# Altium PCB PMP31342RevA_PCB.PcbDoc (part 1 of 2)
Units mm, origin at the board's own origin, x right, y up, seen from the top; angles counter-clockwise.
Board outline 170.18 x 93.98 mm, 4 copper layers (Top Layer, Layer 1, Layer 2, Bottom Layer), stack 1.787 mm thick; 134 components, 50 nets, 251 pads, 234 vias.
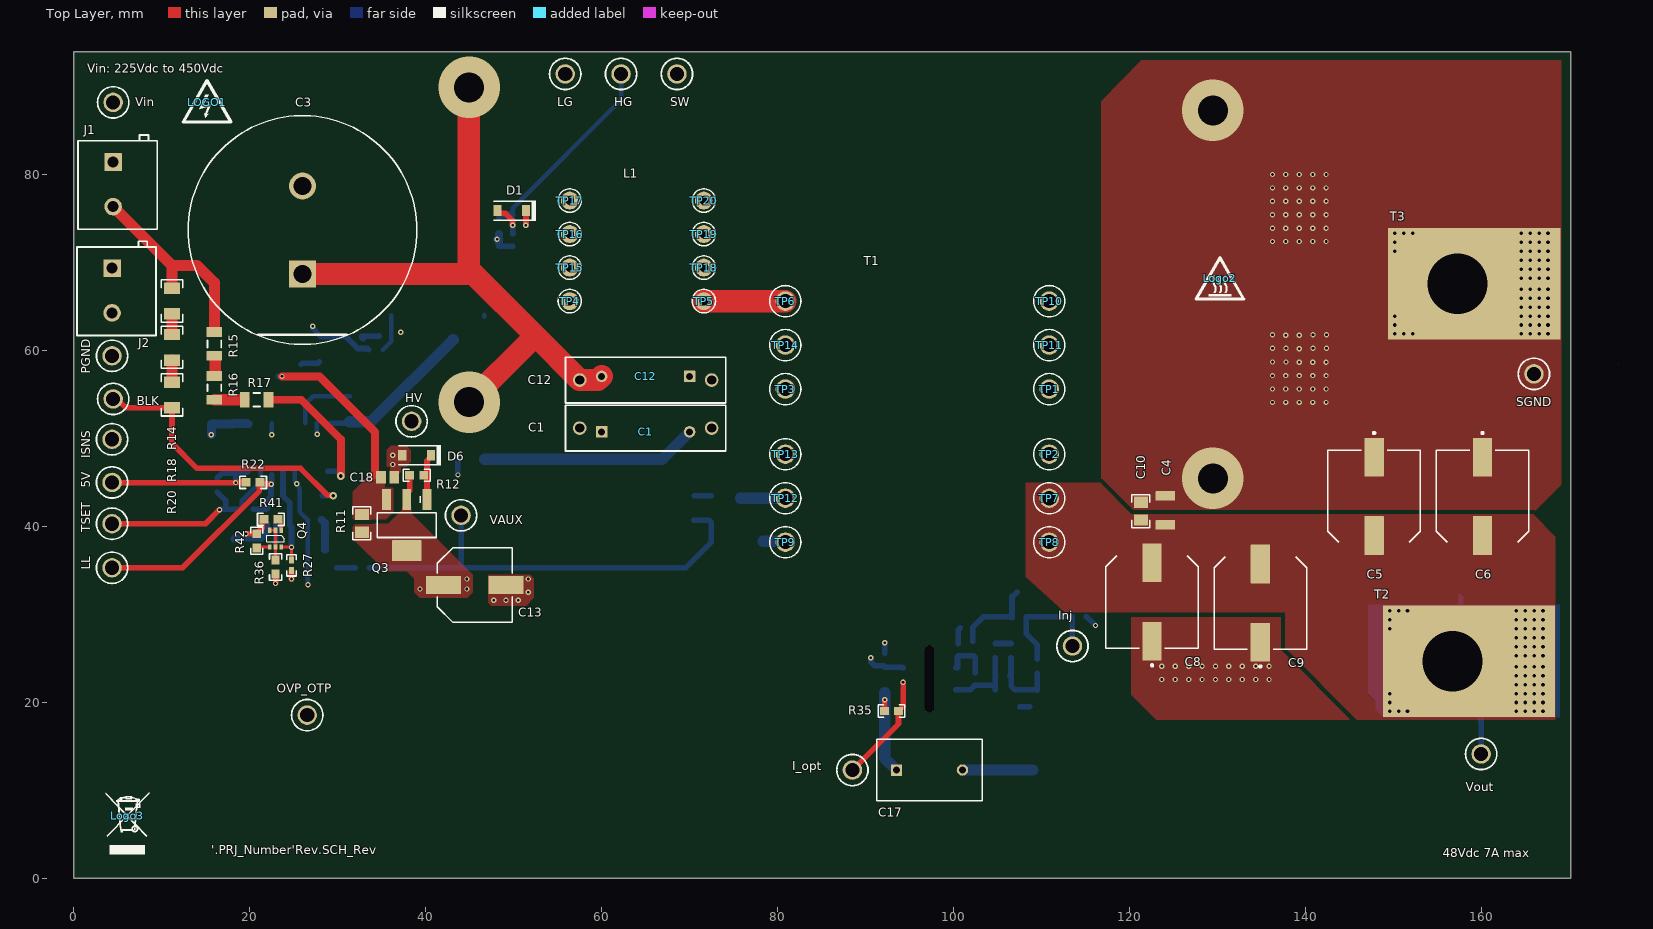
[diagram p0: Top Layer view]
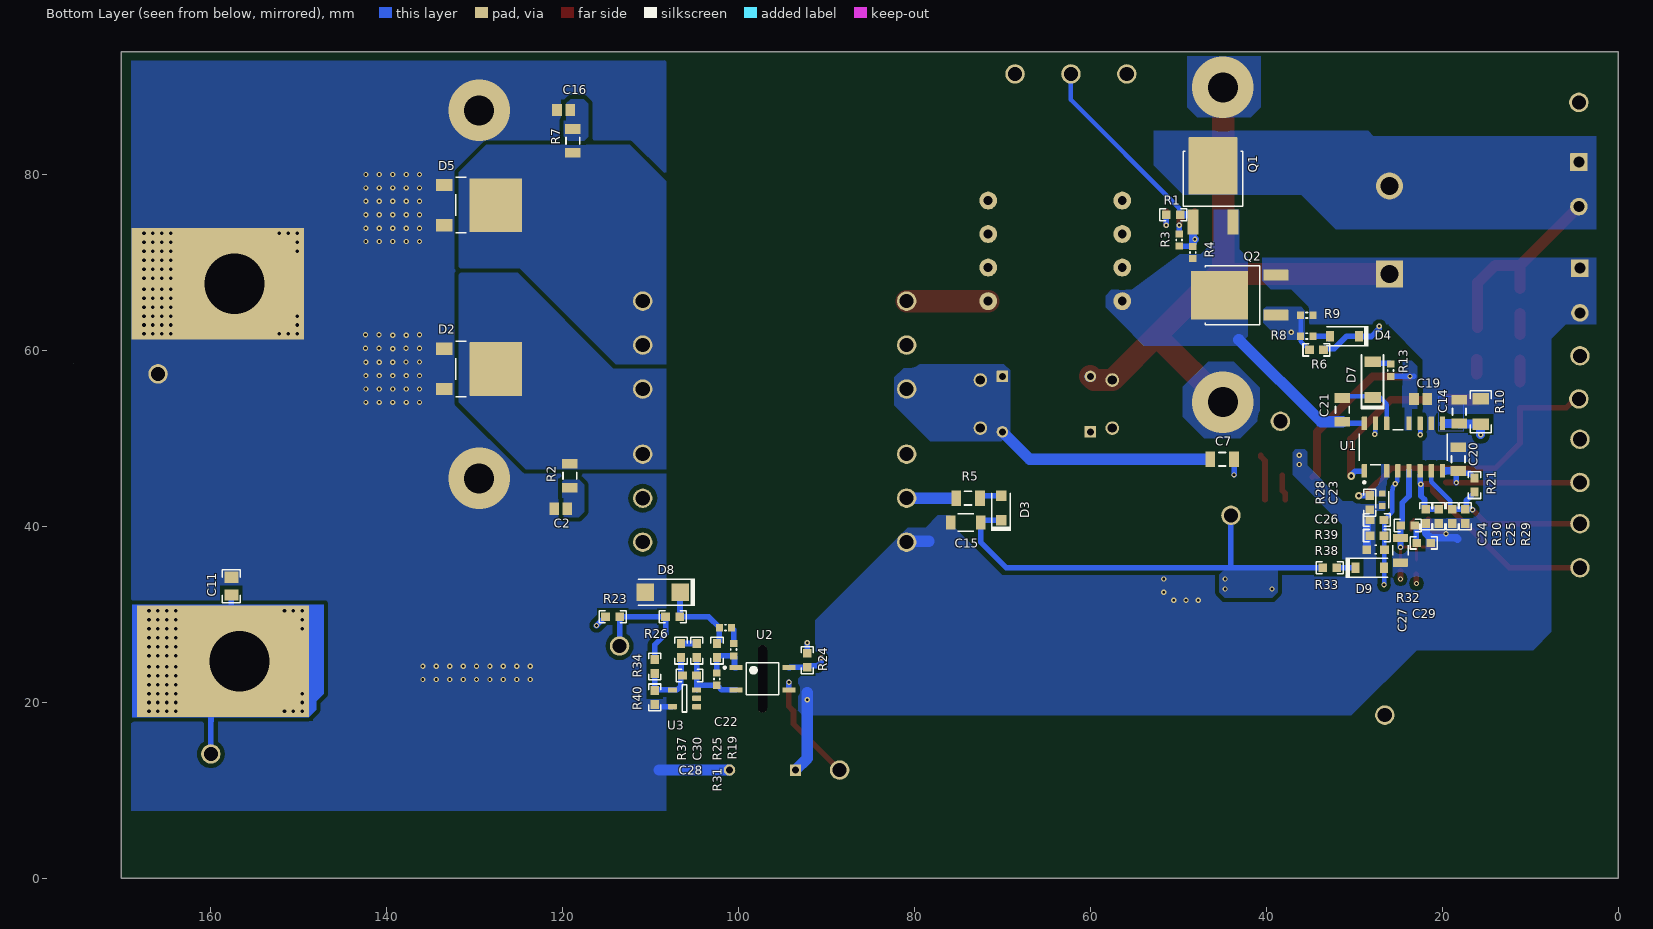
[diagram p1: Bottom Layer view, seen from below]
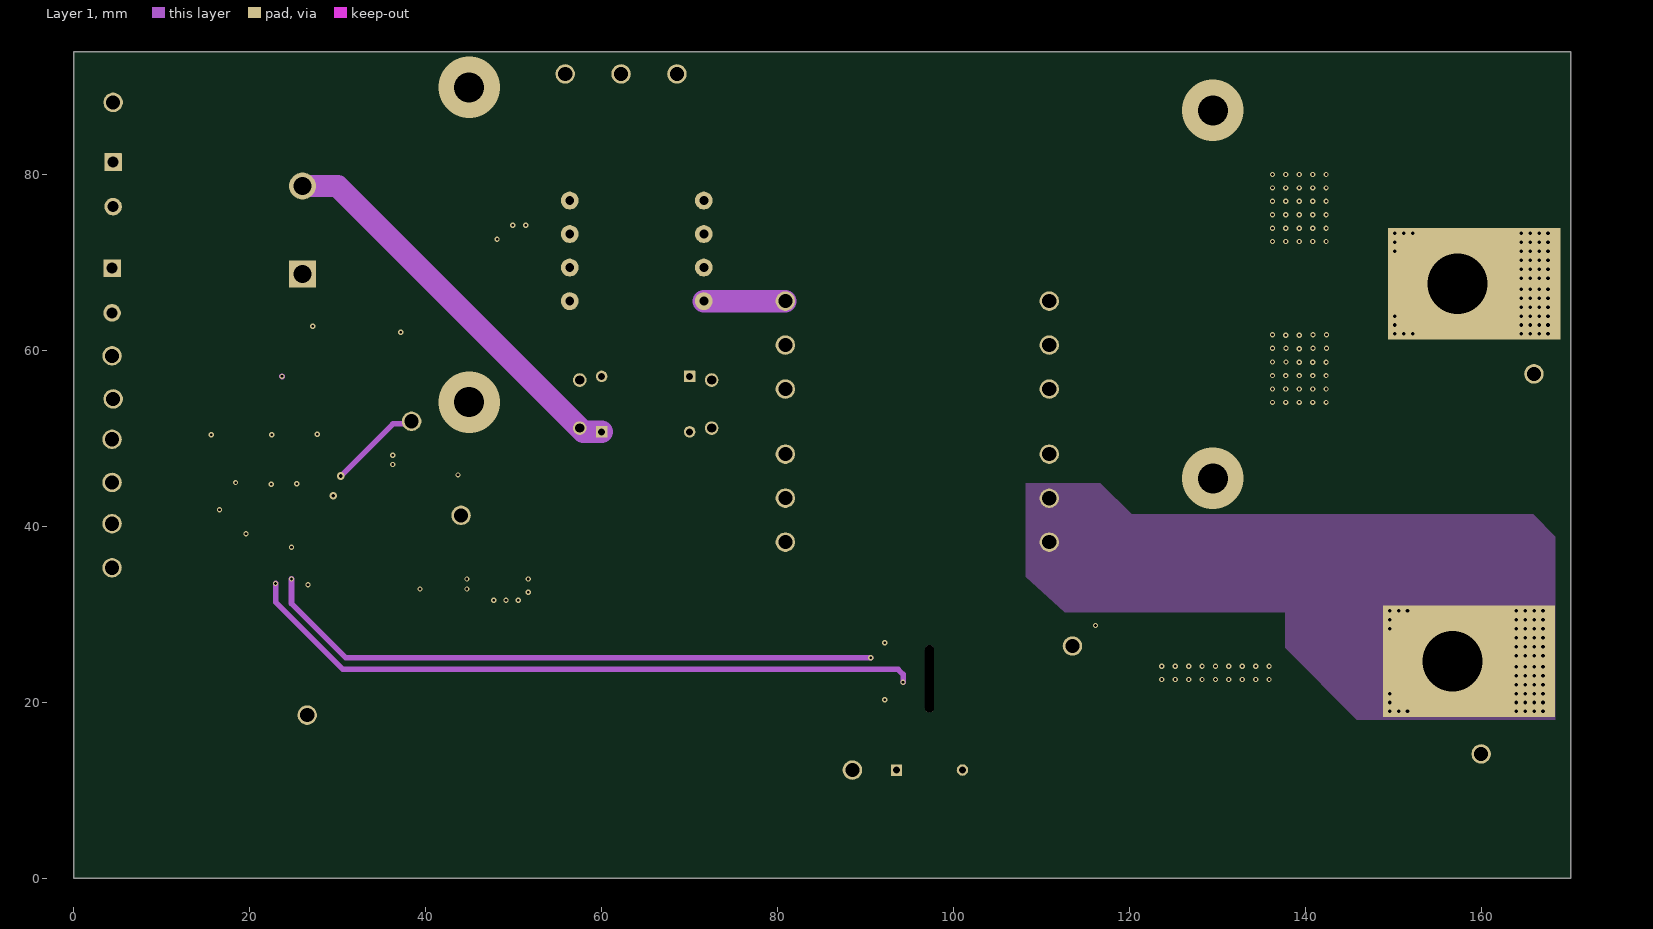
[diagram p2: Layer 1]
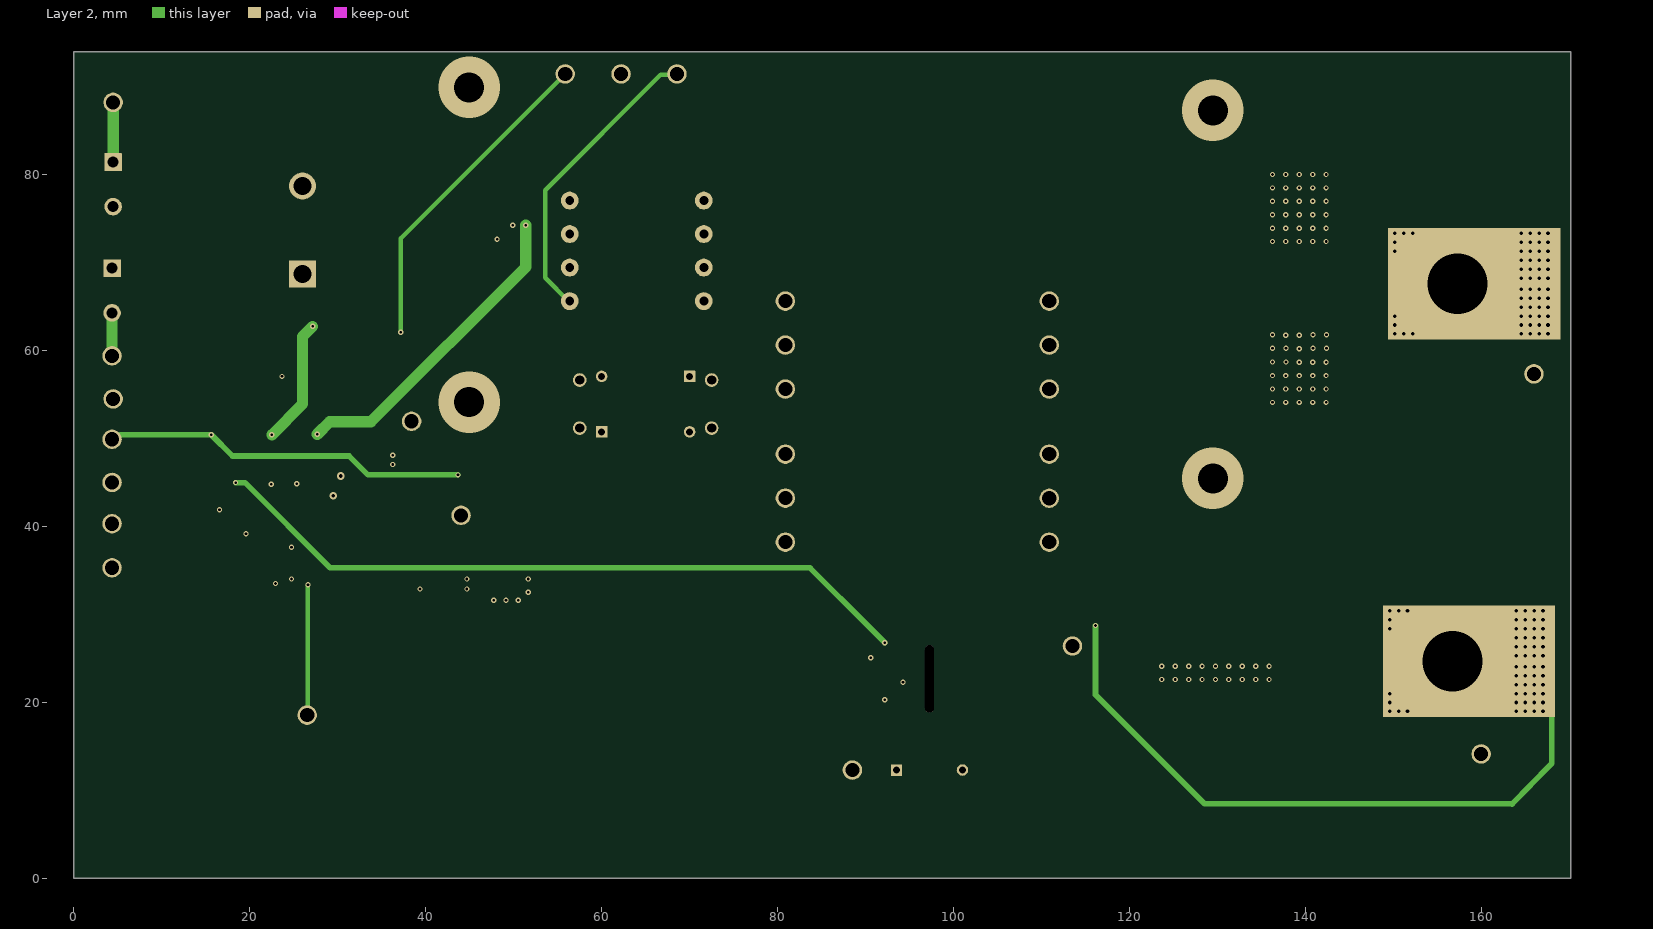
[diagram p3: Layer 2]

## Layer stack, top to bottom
Top Solder: solder mask 0.0102, Solder Resist, Dk 3.5
Top Layer: signal copper 0.0711
Dielectric 1: prepreg 0.0711, PP-006, Dk 4.1
Layer 1: signal copper 0.035
Dielectric1: core 1.4326, FR-4 High Tg, Dk 4.8
Layer 2: signal copper 0.035
Dielectric 2: prepreg 0.0711, PP-006, Dk 4.1
Bottom Layer: signal copper 0.0711
Bottom Solder: solder mask 0.0102, Solder Resist, Dk 3.5

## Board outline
0,-0.006 170.18,-0.006 170.18,93.974 0,93.974

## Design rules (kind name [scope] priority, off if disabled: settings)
AcuteAngle [All] p1: minimum=4.50000000000000E+0001 checktracksonly=FALSE
AssemblyTestPointUsage [All] p1: valid=2
Clearance Clearance_2 [InNetClass('HV') vs Not InNetClass('HV')] p1: gap=1.524 ignorepadtopadclearanceinfootprint=TRUE except(0: Arc-Hole Track-Hole SMDPad-Hole THPad-Hole Via-Hole Fill-Hole Poly-Hole Region-Hole Text-Hole)
Clearance Clearance_1 [InNetClass('MV') vs Not InNetClass('MV')] p2: gap=1.016 ignorepadtopadclearanceinfootprint=TRUE
Clearance Clearance_Keepouts [((IsTrack Or IsArc) And Not InPoly) And IsFree and IsKeepOut vs ((IsTrack Or IsArc) And Not InPoly) And IsFree and IsKeepOut] p3: gap=0 ignorepadtopadclearanceinfootprint=FALSE
Clearance Clearance_BoardEdge_MountingHoles [OnCopper and InComponentClass('Mounting Holes') vs IsKeepOut] p4: gap=1.016 ignorepadtopadclearanceinfootprint=FALSE except(0: Arc-Hole Track-Hole SMDPad-Hole THPad-Hole Via-Hole Fill-Hole Poly-Hole Region-Hole Text-Hole)
Clearance Clearance_BoardEdge_Poly [OnCopper and InPoly vs IsKeepOut] p5: gap=0.635 ignorepadtopadclearanceinfootprint=FALSE except(0: Arc-Hole Track-Hole SMDPad-Hole THPad-Hole Via-Hole Fill-Hole Poly-Hole Region-Hole Text-Hole)
Clearance Clearance_BoardEdge [OnCopper and Not InComponentClass('Logo') and not InComponentClass('FiducialMark') and not InRegion(1000,500,4000,800) and Not IsKeepout vs IsKeepOut] p6: gap=1.905 ignorepadtopadclearanceinfootprint=FALSE except(0: Arc-Hole Track-Hole SMDPad-Hole THPad-Hole Via-Hole Fill-Hole Poly-Hole Region-Hole Text-Hole)
Clearance Clearance_Poly [InPolygon] p7: gap=0.508 ignorepadtopadclearanceinfootprint=FALSE except(0: Arc-Hole Track-Hole SMDPad-Hole THPad-Hole Via-Hole Fill-Hole Poly-Hole Region-Hole Text-Hole)
Clearance [All] p8: gap=0.2 ignorepadtopadclearanceinfootprint=FALSE except(0: Arc-SMDPad Arc-Hole Track-Hole SMDPad-Hole THPad-Hole Via-Hole Fill-Hole Poly-Hole Region-Hole Text-Hole)
ComponentClearance ComponentClearance_MountingHoles_FiducialMarks [InComponentClass('Mounting Holes') vs InComponentClass('FiducialMark')] p1: gap=0.508 collisioncheckmode=3 verticalgap=0.178 showdistances=FALSE
ComponentClearance ComponentClearance_Shunt [InComponentClass('Header') vs InComponentClass('Shunt')] p2: gap=0 collisioncheckmode=3 verticalgap=0 showdistances=FALSE
ComponentClearance ComponentClearance_Logo [InComponentClass('Logo')] p3: gap=0.127 collisioncheckmode=3 verticalgap=0.254 showdistances=FALSE
ComponentClearance ComponentClearance_ScrewToNut [(HasFootprint('KEYSTONE_4824')) vs (HasFootprint('Keystone_1903C'))] p4: gap=0 collisioncheckmode=3 verticalgap=0 showdistances=FALSE
ComponentClearance ComponentClearance_MountingHoles [InComponentClass('Mounting Holes')] p5: gap=0.508 collisioncheckmode=3 verticalgap=0.178 showdistances=FALSE
ComponentClearance ComponentClearance_SmallPassives [HasFootprint('0201*') or HasFootprint('0402*') or HasFootprint('0508') or HasFootprint('0603*') or HasFootprint('0612') or HasFootprint('0805*') or HasFootprint('0815*') or HasFootprint('0830*') or HasFootprint('1206*') or HasFootprint('1210*') or HasFootprint('1808*') or HasFootprint('1812*') or HasFootprint('1825*') or HasFootprint('2010*') or HasFootprint('2220*') or HasFootprint('2225*') or HasFootprint('2512*') or HasFootprint('2728*') or HasFootprint('3518*') vs HasFootprint('0201*') or HasFootprint('0402*') or HasFootprint('0508') or HasFootprint('0603*') or HasFootprint('0612') or HasFootprint('0805*') or HasFootprint('0815*') or HasFootprint('0830*') or HasFootprint('1206*') or HasFootprint('1210*') or HasFootprint('1808*') or HasFootprint('1812*') or HasFootprint('1825*') or HasFootprint('2010*') or HasFootprint('2220*') or HasFootprint('2225*') or HasFootprint('2512*') or HasFootprint('2728*') or HasFootprint('3518*')] p6: gap=0.508 collisioncheckmode=3 verticalgap=0.508 showdistances=FALSE
ComponentClearance ComponentClearance_THtoSMT [IsThruComponent vs IsSMTComponent] p7: gap=0.254 collisioncheckmode=3 verticalgap=0.178 showdistances=FALSE
ComponentClearance ComponentClearance_THtoTH [IsThruComponent vs IsThruComponent] p8: gap=0.254 collisioncheckmode=3 verticalgap=0.178 showdistances=FALSE
ComponentClearance [All] p9: gap=0.254 collisioncheckmode=3 verticalgap=0.178 showdistances=FALSE
DiffPairsRouting [All] p1: maxlimit=2.54 minlimit=0.254 mostfreqgap=0.254 toplayer_minwidth=0.381 toplayer_maxwidth=0.381 toplayer_prefwidth=0.381 midlayer1_minwidth=0.381 midlayer1_maxwidth=0.381 midlayer1_prefwidth=0.381 midlayer2_minwidth=0.381 midlayer2_maxwidth=0.381 midlayer2_prefwidth=0.381 bottomlayer_minwidth=0.381 bottomlayer_maxwidth=0.381 bottomlayer_prefwidth=0.381 maxuncoupledlength=25.4
FabricationTestPointUsage TestPointUsage [All] p1: valid=2 allowmultiple=FALSE
FabricationTestpoint Testpoint [All] p1: side=3 testpointundercomponent=TRUE minsize=1.016 maxsize=2.54 preferedsize=1.524 minholesize=0 maxholesize=1.016 preferedholesize=0.813 testpointgrid=0.025 allowsidetop=TRUE allowsidebottom=TRUE usegrid=TRUE gridtolerance=0
FanoutControl Fanout_LCC [IsLCC] p1: bgadir=Out bgaviamode=Centered fanoutstyle=Auto fanoutdirection=Alternating viagrid=0.025 // Fanout_LCC (Default Rule)
FanoutControl Fanout_BGA [IsBGA] p2: bgadir=Out bgaviamode=Centered fanoutstyle=Auto fanoutdirection=Alternating viagrid=0.025 // Fanout_BGA (Default Rule)
FanoutControl Fanout_Default [All] p4: bgadir=Out bgaviamode=Centered fanoutstyle=Auto fanoutdirection=Alternating viagrid=0.025 // Fanout_Default (Default Rule)
FanoutControl Fanout_Small [(CompPinCount < 5)] p5: bgadir=Out bgaviamode=Centered fanoutstyle=Auto fanoutdirection=OutThenIn viagrid=0.025 // Fanout_Small (Default Rule)
Height [All] p1: minheight=0 maxheight=76.2 prefheight=12.7
HoleSize [All] p1: absolutevalues=TRUE maxlimit=12.725 minlimit=0.178 maxpercent=80.000 minpercent=20.000
MinimumAnnularRing MinimumAnnularRing_ThermalPadVias [IsVia and InAnyComponent] p1: minimumring=0.15
MinimumAnnularRing [All] p2: minimumring=0.127
MinimumSolderMaskSliver MinimumSolderMaskSliver_Logo [InComponentClass('Logo') vs InComponentClass('Logo')] p1: minsoldermaskwidth=0.018
MinimumSolderMaskSliver [All] p2: minsoldermaskwidth=0.076
PlaneConnect [All] p1: planeconnectstyle=Direct reliefexpansion=0.254 reliefentries=4 reliefconductorwidth=0.254 reliefairgap=0.254
PolygonConnect PolygonConnect_16 [All vs IsNamedPolygon('C106_2') Or  IsNamedPolygon('Vout') Or  IsNamedPolygon('IN+') Or  IsNamedPolygon('Q203_5') Or  IsNamedPolygon('IN+') Or  IsNamedPolygon('Q201_5') Or  IsNamedPolygon('C108_2') Or  IsNamedPolygon('SGND') Or  IsNamedPolygon('IN+') Or  IsNamedPolygon('SGND') Or  IsNamedPolygon('Q203_5') Or  IsNamedPolygon('IN+') Or  IsNamedPolygon('SGND') Or  IsNamedPolygon('GND') Or  IsNamedPolygon('C113_2') Or  IsNamedPolygon('C107_2') Or  IsNamedPolygon('C107_2') Or  IsNamedPolygon('Vout') Or  IsNamedPolygon('SIGNAL_LAYER_1_GND_P074') Or  IsNamedPolygon('HV') Or  IsNamedPolygon('C108_2') Or  IsNamedPolygon('C103_2') Or  IsNamedPolygon('Q201_5') Or  IsNamedPolygon('Vout') Or  IsNamedPolygon('C109_2') Or  IsNamedPolygon('Q201_5') Or  IsNamedPolygon('GND') Or  IsNamedPolygon('C107_2') Or  IsNamedPolygon('C102_1') Or  IsNamedPolygon('GND') Or  IsNamedPolygon('SGND') Or  IsNamedPolygon('HS') Or  IsNamedPolygon('Q203_5') Or  IsNamedPolygon('Q201_5') Or  IsNamedPolygon('Q203_5')] p1: connectstyle=Direct reliefconductorwidth=0.254 reliefentries=4 polygonreliefangle="90 Angle" airgapwidth=0.254
PolygonConnect PolygonConnect_15 [All vs IsNamedPolygon('C109_2') Or  IsNamedPolygon('C107_2') Or  IsNamedPolygon('HV') Or  IsNamedPolygon('Q203_5') Or  IsNamedPolygon('C107_2') Or  IsNamedPolygon('HS') Or  IsNamedPolygon('Q201_5') Or  IsNamedPolygon('Q203_5') Or  IsNamedPolygon('C106_2') Or  IsNamedPolygon('C108_2') Or  IsNamedPolygon('Vout') Or  IsNamedPolygon('Q203_5') Or  IsNamedPolygon('C108_2') Or  IsNamedPolygon('C113_2') Or  IsNamedPolygon('Q203_5') Or  IsNamedPolygon('Q201_5') Or  IsNamedPolygon('C107_2') Or  IsNamedPolygon('C102_1') Or  IsNamedPolygon('SGND') Or  IsNamedPolygon('GND') Or  IsNamedPolygon('SGND') Or  IsNamedPolygon('GND') Or  IsNamedPolygon('IN+') Or  IsNamedPolygon('IN+') Or  IsNamedPolygon('Q201_5') Or  IsNamedPolygon('Q201_5') Or  IsNamedPolygon('SGND') Or  IsNamedPolygon('SGND') Or  IsNamedPolygon('Vout') Or  IsNamedPolygon('Vout') Or  IsNamedPolygon('IN+') Or  IsNamedPolygon('GND') Or  IsNamedPolygon('IN+') Or  IsNamedPolygon('GND')] p2: connectstyle=Direct reliefconductorwidth=0.254 reliefentries=4 polygonreliefangle="90 Angle" airgapwidth=0.254
PolygonConnect PolygonConnect_14 [All vs IsNamedPolygon('C106_2') Or  IsNamedPolygon('C107_2') Or  IsNamedPolygon('C107_2') Or  IsNamedPolygon('C107_2') Or  IsNamedPolygon('C102_1') Or  IsNamedPolygon('Q203_5') Or  IsNamedPolygon('Vout') Or  IsNamedPolygon('Q203_5') Or  IsNamedPolygon('Q203_5') Or  IsNamedPolygon('Q201_5') Or  IsNamedPolygon('C108_2') Or  IsNamedPolygon('Q203_5') Or  IsNamedPolygon('HS') Or  IsNamedPolygon('HV') Or  IsNamedPolygon('C108_2') Or  IsNamedPolygon('Q201_5') Or  IsNamedPolygon('C109_2') Or  IsNamedPolygon('Q201_5') Or  IsNamedPolygon('Q201_5') Or  IsNamedPolygon('C113_2')] p3: connectstyle=Direct reliefconductorwidth=0.254 reliefentries=4 polygonreliefangle="90 Angle" airgapwidth=0.254
PolygonConnect PolygonConnect_13 [All vs IsNamedPolygon('C102_1') Or  IsNamedPolygon('HV') Or  IsNamedPolygon('C107_2') Or  IsNamedPolygon('C109_2') Or  IsNamedPolygon('C107_2') Or  IsNamedPolygon('C108_2') Or  IsNamedPolygon('C106_2') Or  IsNamedPolygon('C108_2') Or  IsNamedPolygon('C113_2') Or  IsNamedPolygon('C107_2')] p4: connectstyle=Direct reliefconductorwidth=0.254 reliefentries=4 polygonreliefangle="90 Angle" airgapwidth=0.254
PolygonConnect PolygonConnect_12 [All vs IsNamedPolygon('C107_2') Or  IsNamedPolygon('C113_2') Or  IsNamedPolygon('C106_2') Or  IsNamedPolygon('C107_2') Or  IsNamedPolygon('C107_2') Or  IsNamedPolygon('C102_1')] p5: connectstyle=Direct reliefconductorwidth=0.254 reliefentries=4 polygonreliefangle="90 Angle" airgapwidth=0.254
PolygonConnect PolygonConnect_11 [All vs IsNamedPolygon('C106_2') Or  IsNamedPolygon('C102_1') Or  IsNamedPolygon('C107_2') Or  IsNamedPolygon('C107_2') Or  IsNamedPolygon('C107_2')] p6: connectstyle=Direct reliefconductorwidth=0.254 reliefentries=4 polygonreliefangle="90 Angle" airgapwidth=0.254
PolygonConnect PolygonConnect_10 [All vs IsNamedPolygon('C106_2')] p7: connectstyle=Direct reliefconductorwidth=0.254 reliefentries=4 polygonreliefangle="90 Angle" airgapwidth=0.254
PolygonConnect PolygonConnect_9 [All vs IsNamedPolygon('C11_1') Or  IsNamedPolygon('Vin') Or  IsNamedPolygon('Vin') Or  IsNamedPolygon('5V') Or  IsNamedPolygon('D6_2') Or  IsNamedPolygon('Q3_3') Or  IsNamedPolygon('GND2') Or  IsNamedPolygon('GND2') Or  IsNamedPolygon('GND') Or  IsNamedPolygon('Q3_4') Or  IsNamedPolygon('12V5') Or  IsNamedPolygon('GND') Or  IsNamedPolygon('12V5') Or  IsNamedPolygon('D3_1')] p8: connectstyle=Direct reliefconductorwidth=0.254 reliefentries=4 polygonreliefangle="90 Angle" airgapwidth=0.254
PolygonConnect PolygonConnect_8 [All vs IsNamedPolygon('C11_1') Or  IsNamedPolygon('Vin') Or  IsNamedPolygon('12V5') Or  IsNamedPolygon('Q3_3') Or  IsNamedPolygon('GND2') Or  IsNamedPolygon('GND2') Or  IsNamedPolygon('5V') Or  IsNamedPolygon('Q3_4') Or  IsNamedPolygon('12V5')] p9: connectstyle=Direct reliefconductorwidth=0.254 reliefentries=4 polygonreliefangle="90 Angle" airgapwidth=0.254
PolygonConnect PolygonConnect_7 [All vs IsNamedPolygon('GND2') Or  IsNamedPolygon('GND2') Or  IsNamedPolygon('5V') Or  IsNamedPolygon('12V5') Or  IsNamedPolygon('12V5') Or  IsNamedPolygon('C11_1')] p10: connectstyle=Direct reliefconductorwidth=0.254 reliefentries=4 polygonreliefangle="90 Angle" airgapwidth=0.254
PolygonConnect PolygonConnect_6 [All vs IsNamedPolygon('GND2') Or  IsNamedPolygon('SGND') Or  IsNamedPolygon('GND1') Or  IsNamedPolygon('C901_1') Or  IsNamedPolygon('SGND') Or  IsNamedPolygon('GND2') Or  IsNamedPolygon('GND1')] p11: connectstyle=Direct reliefconductorwidth=0.254 reliefentries=4 polygonreliefangle="90 Angle" airgapwidth=0.254
PolygonConnect PolygonConnect_5 [All vs IsNamedPolygon('GND1') Or  IsNamedPolygon('GND1')] p12: connectstyle=Direct reliefconductorwidth=0.254 reliefentries=4 polygonreliefangle="90 Angle" airgapwidth=0.254
PolygonConnect PolygonConnect_4 [All vs IsNamedPolygon('C21_1') Or  IsNamedPolygon('C5_1') Or  IsNamedPolygon('C12_2') Or  IsNamedPolygon('C2_2') Or  IsNamedPolygon('C13_1') Or  IsNamedPolygon('C28_1') Or  IsNamedPolygon('C6_1') Or  IsNamedPolygon('GND') Or  IsNamedPolygon('GND2') Or  IsNamedPolygon('C14_1') Or  IsNamedPolygon('C13_1') Or  IsNamedPolygon('Q1_3') Or  IsNamedPolygon('C14_1') Or  IsNamedPolygon('C5_1') Or  IsNamedPolygon('GND2') Or  IsNamedPolygon('C28_1') Or  IsNamedPolygon('D5_2') Or  IsNamedPolygon('D6_2') Or  IsNamedPolygon('D2_1') Or  IsNamedPolygon('C12_2') Or  IsNamedPolygon('D2_1') Or  IsNamedPolygon('C4_1') Or  IsNamedPolygon('C4_1') Or  IsNamedPolygon('C2_2') Or  IsNamedPolygon('GND') Or  IsNamedPolygon('C33_1') Or  IsNamedPolygon('C9_1')] p13: connectstyle=Direct reliefconductorwidth=0.254 reliefentries=4 polygonreliefangle="90 Angle" airgapwidth=0.254
PolygonConnect PolygonConnect_3 [All vs IsNamedPolygon('C28_1') Or  IsNamedPolygon('C12_2') Or  IsNamedPolygon('C28_1') Or  IsNamedPolygon('C9_1') Or  IsNamedPolygon('D5_2') Or  IsNamedPolygon('C12_2') Or  IsNamedPolygon('C2_2') Or  IsNamedPolygon('C14_1') Or  IsNamedPolygon('C4_1') Or  IsNamedPolygon('C14_1') Or  IsNamedPolygon('D6_2') Or  IsNamedPolygon('GND2') Or  IsNamedPolygon('Q1_3') Or  IsNamedPolygon('C5_1') Or  IsNamedPolygon('D2_1') Or  IsNamedPolygon('C4_1') Or  IsNamedPolygon('C13_1') Or  IsNamedPolygon('C5_1') Or  IsNamedPolygon('C13_1') Or  IsNamedPolygon('C33_1') Or  IsNamedPolygon('D2_1') Or  IsNamedPolygon('GND') Or  IsNamedPolygon('GND') Or  IsNamedPolygon('GND2') Or  IsNamedPolygon('C2_2') Or  IsNamedPolygon('C6_1') Or  IsNamedPolygon('C21_1')] p14: connectstyle=Direct reliefconductorwidth=0.254 reliefentries=4 polygonreliefangle="90 Angle" airgapwidth=0.254
PolygonConnect PolygonConnect_2 [All vs IsNamedPolygon('C21_1') Or  IsNamedPolygon('C4_1') Or  IsNamedPolygon('D5_2') Or  IsNamedPolygon('C5_1') Or  IsNamedPolygon('C14_1') Or  IsNamedPolygon('C13_1') Or  IsNamedPolygon('C4_1') Or  IsNamedPolygon('C33_1') Or  IsNamedPolygon('C12_2') Or  IsNamedPolygon('D2_1') Or  IsNamedPolygon('C2_2') Or  IsNamedPolygon('C28_1') Or  IsNamedPolygon('C12_2') Or  IsNamedPolygon('D2_1') Or  IsNamedPolygon('C5_1') Or  IsNamedPolygon('Q1_3') Or  IsNamedPolygon('GND') Or  IsNamedPolygon('D6_2') Or  IsNamedPolygon('C6_1') Or  IsNamedPolygon('C2_2') Or  IsNamedPolygon('C14_1') Or  IsNamedPolygon('C28_1') Or  IsNamedPolygon('C13_1') Or  IsNamedPolygon('C9_1') Or  IsNamedPolygon('GND')] p15: connectstyle=Direct reliefconductorwidth=0.254 reliefentries=4 polygonreliefangle="90 Angle" airgapwidth=0.254
PolygonConnect PolygonConnect_1 [All vs IsNamedPolygon('C28_1') Or  IsNamedPolygon('D5_2') Or  IsNamedPolygon('C5_1') Or  IsNamedPolygon('C5_1') Or  IsNamedPolygon('D2_1') Or  IsNamedPolygon('C21_1') Or  IsNamedPolygon('C9_1') Or  IsNamedPolygon('C4_1') Or  IsNamedPolygon('C14_1') Or  IsNamedPolygon('C28_1') Or  IsNamedPolygon('C6_1') Or  IsNamedPolygon('C12_2') Or  IsNamedPolygon('C33_1') Or  IsNamedPolygon('C4_1') Or  IsNamedPolygon('C13_1') Or  IsNamedPolygon('C12_2') Or  IsNamedPolygon('D6_2') Or  IsNamedPolygon('C2_2') Or  IsNamedPolygon('C14_1') Or  IsNamedPolygon('D2_1') Or  IsNamedPolygon('C2_2') Or  IsNamedPolygon('C13_1')] p16: connectstyle=Direct reliefconductorwidth=0.254 reliefentries=4 polygonreliefangle="90 Angle" airgapwidth=0.254
PolygonConnect [All] p17: connectstyle=Direct reliefconductorwidth=0.254 reliefentries=4 polygonreliefangle="90 Angle" airgapwidth=0.254
RoutingVias ThermalPadVias [IsVia and not InNet('SGND')and not InNet('Vout')] p1: holewidth=0.2 width=0.5 viastyle="Through Hole" minholewidth=0.2 minwidth=0.5 maxholewidth=0.432 maxwidth=0.889
RoutingVias [IsVia and not InNet('SGND')and not InNet('Vout')] p2: holewidth=0.406 width=0.864 viastyle="Through Hole" minholewidth=0.2 minwidth=0.508 maxholewidth=1.016 maxwidth=1.651
SilkToBoardRegionClearance [Not ((IsComment or IsDesignator) And (Hide <> 'False')) and not InRegion(1000,500,4000,800)] p1:
SilkToSilkClearance SilkToSilkClearance_Pb-FreeLogo [(HasFootprint('Pb-Free_Overlay_Medium') OR HasFootprint('Pb-Free_Overlay_Small')) vs (HasFootprint('Pb-Free_Overlay_Medium') OR HasFootprint('Pb-Free_Overlay_Small'))] p1: silktosilkclearance=0
SilkToSilkClearance [All] p2: silktosilkclearance=0.076
SilkToSolderMaskClearance "Silk to Solder Mask Opening" [All] p1: minsilkscreentomaskgap=0.025 clearancetoexposedcopper=FALSE
SolderMaskExpansion [All] p1: expansion=0.05 istentingtop=FALSE
SupplyNets "Schematic Supply Nets_1" [InNet('SGND')] p1: voltage=0.000
SupplyNets "Schematic Supply Nets" [InNet('PGND')] p2: voltage=0.000
UnpouredPolygon [All] p1: allowunpoured=TRUE allowshelved=TRUE
Width [All] p1: maxlimit=2.54 minlimit=0.152 preferedwidth=0.254 checkconnectedcopper=TRUE
13 further rules are at their usual default settings.

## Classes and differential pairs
net class MV: NetR14_1 NetR18_1
net class HV: HO HS NetC1_2 NetC21_1 NetD1_2 NetHG_1 NetHV_1 VIN
component class PMP31342RevA_Control: 5V BLK C18 C19 C20 C21 C22 C23 C24 C25 C26 C27 C28 C29 C30 D6 D7 D8 D9 HV I_opt Inj LL OVP_OTP Q3 Q4 R11 R12 R13 R14 R15 R16 R17 R18 R19 R20 R21 R22 R23 R24 R25 R26 R27 R28 R29 R30 R31 R32 R33 R34 R35 R36 R37 R38 R39 R40 R41 R42 TSET U1 U2 U3 Vout
component class PMP31342RevA_PowerStage: C1 C2 C3 C4 C5 C6 C7 C8 C9 C10 C11 C12 C13 C14 C15 C16 C17 D1 D2 D3 D4 D5 HG ISNS J1 J2 LG LOGO1 Logo2 Logo3 PGND Q1 Q2 R1 R2 R3 R4 R5 R6 R7 R8 R9 R10 SGND SW T2 T3 TP1 TP2 TP3 TP4 TP5 TP6 TP7 TP8 TP9 TP10 TP11 TP12 TP13 TP14 TP15 TP16 TP17 TP18 TP19 TP20 VAUX Vin

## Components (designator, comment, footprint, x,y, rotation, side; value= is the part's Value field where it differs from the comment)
5V "5010" Keystone5010 4.369,45.008 r0 top
BLK "5012" Keystone5012 4.496,54.499 r90 top
C1 "B32641B1682J000" FP-B32641B1682J000_RADIAL-MFG 65.024,50.76 r0 top
C1 "B32641B6333" CAPRR1500W80L1800T500H1050 65.024,51.181 r0 top value=0.033uF
C2 "GRM2165C2A122JA01D" 0805L 120.213,42.028 r0 bottom value=1200pF
C3 "ALA8AD121BC500" FP-ALA8AD121BC500_RADIAL-MFG 26.016,73.698 r90 top value=120µF
C4 "CNA6P1X7R2A475K250AE" FP-CNA6P1X7R2A475K250AE_1210-MFG 124.104,41.828 r270 top
C5 "HHXF630ARA820MJA0G" FP-HHXF630ARA820MJA0G_RADIAL-MFG 147.828,43.428 r270 top value=82µF
C6 "HHXF630ARA820MJA0G" FP-HHXF630ARA820MJA0G_RADIAL-MFG 160.147,43.428 r270 top value=82µF
C7 "GRM31A5C2J151JW01D" 1206L 45.034,47.648 r180 bottom value=150pF
C8 "HHXF630ARA820MJA0G" FP-HHXF630ARA820MJA0G_RADIAL-MFG 122.58,31.414 r90 top value=82µF
C9 "HHXF630ARA820MJA0G" FP-HHXF630ARA820MJA0G_RADIAL-MFG 134.899,31.287 r90 top value=82µF
C10 "GCM21BR72A104KA37L" 0805_HV 121.31,41.734 r90 top value=0.1uF
C11 "GCM2165C2A101JA16D" 0805_HV 157.658,33.217 r90 bottom value=100pF
C12 "B32641B1682J000" FP-B32641B1682J000_RADIAL-MFG 65.024,57.063 r180 top
C12 "B32641B6333" CAPRR1500W80L1800T500H1050 65.024,56.642 r180 top value=0.033uF
C13 "EEE-FK1E331P" SM_RADIAL_F 45.593,33.344 r0 top value=330uF
C14 "12061A101JAT2A" 1206L 18.085,53.045 r90 bottom value=100pF
C15 "C1206C106J3RACAUTO" 1206_180 74.184,40.454 r0 bottom value=10uF
C16 "GRM2165C2A122JA01D" 0805L 119.888,87.345 r0 bottom value=1200pF
C17 "CS95ZU2GA332MANKA" FP-CS95ZU2GA332MANKA_RADIAL-MFG 97.282,12.313 r0 top value=3.3nF
C18 "C2012X7R1V225K085AC" 0805L 35.693,45.592 r180 top value=2.2uF
C19 "C2012X7R1V225K085AC" 0805L 22.486,54.495 r180 bottom value=2.2uF
C20 "C3216X7R1E475K085AB" 1206L 18.205,47.648 r90 bottom value=4.7uF
C21 "GRM31C5C1E104JA01L" 1206_180L 31.369,53.258 r270 bottom value=0.1uF
C22 "C0603C472J1GAC7867" 0603L 101.492,28.501 r180 bottom value=4700pF
C23 "CGA3E2X7R1H103K080AA" FP-CGA3E2X7R1H103K080AA_0603-MFG 26.834,43.032 r90 bottom value=10nF
C24 "C0603X102K5RACTU" 0603 21.876,41.153 r270 bottom value=1000pF
C25 "C0603X221K5RACTU" 0603 18.877,41.153 r270 bottom value=220pF
C26 "C0603X222K5RACTU" 0603 27.445,40.735 r0 bottom value=2200pF
C27 "C1206C302J5GACTU" FP-C1206C302J5GACTU_1206-MFG 24.768,37.288 r270 bottom value=3pF
C28 "GRM188R72A681KA01D" 0603 105.588,23.057 r180 bottom value=680pF
C29 "C0603X102K5RACTU" 0603 22.116,38.127 r180 bottom value=1000pF
C30 "GCM188R71E473KA37D" 0603 104.776,25.893 r270 bottom value=0.047uF
D1 "1N4148W-7-F" SOD-123 49.797,75.907 r180 top value=100V
D2 "V35PWM153HM3/I" FP-V35PWM153-M3_I_TO-252AE-MFG 129.507,57.906 r270 bottom
D3 "PMEG10020ELRX" SOD-123W 70.171,42.111 r90 bottom value=100V
D4 "1N4148W-7-F" SOD-123 31.127,61.626 r0 bottom value=100V
D5 "V35PWM153HM3/I" FP-V35PWM153-M3_I_TO-252AE-MFG 129.507,76.524 r270 bottom
D6 "MMSZ5250B-7-F" SOD-123 38.989,48.084 r180 top value=20V
D7 "ES1JAF" SMAF 27.94,56.687 r90 bottom value=600V
D8 "SMAZ18-13-F" SMA 108.613,32.506 r0 bottom value=18V
D9 "MMSZ4704-HE3-08" SOD-123 28.263,35.295 r180 bottom value=17V
HG "5012" Keystone5012 62.23,91.44 r0 top
HV "5012" Keystone5012 38.419,51.956 r0 top (schematic designator HV1)
I_opt "5012" Keystone5012 88.519,12.313 r0 top
Inj "5013" Keystone5013 113.538,26.41 r0 top (schematic designator INJ)
ISNS "5012" Keystone5012 4.369,49.911 r0 top
J1 "ED120/2DS" On-Shore_ED120_2DS 4.496,78.887 r270 top
J2 "ED120/2DS" On-Shore_ED120_2DS 4.369,66.822 r270 top
LG "5012" Keystone5012 55.88,91.44 r270 top
LL "5012" Keystone5012 4.369,35.306 r0 top
LOGO1 "DANGER HIGH VOLTAGE" IEC_HighVoltage_Small 15.165,88.208 r0 top
Logo2 "CAUTION HOT SURFACE" IEC_HotSurface_Small 130.302,68.199 r0 top
Logo3 "WEEE logo" WEEE_Minimum 6.096,7.112 r0 top
OVP_OTP "5012" Keystone5012 26.551,18.553 r0 top
PGND "5011" Keystone5011 4.369,59.401 r0 top (schematic designator PGND1)
Q1 "NVB190N65S3F" FP-FDD86252_D2PAK-MFG 46.076,78.709 r180 bottom
Q2 "NVB190N65S3F" FP-FDD86252_D2PAK-MFG 43.049,66.289 r90 bottom
Q3 "FZT651TA" SOT-223 37.866,40.154 r270 top value="60 V"
Q4 "MMDT3904-7-F" SOT-363 22.951,38.622 r270 top value="40 V"
R1 "CRCW06034R70JNEA" 0603 50.597,75.432 r180 bottom value=4.7
R2 "RC1206FR-0710RL" 1206L 119.185,45.769 r90 bottom value=10.0
R3 "RC0603FR-071RL" 0603L 49.917,72.559 r270 bottom value=1.00
R4 "RC0603FR-0751KL" 0603L 48.356,71.148 r90 bottom value=51.0k
R5 "ERJ-8GEY0R00V" 1206L 73.914,43.216 r0 bottom value=0
R6 "CRCW06034R70JNEA" 0603 34.321,60.068 r0 bottom value=4.7
R7 "RC1206FR-0710RL" 1206L 118.847,83.84 r270 bottom value=10.0
R8 "RC0603FR-071RL" 0603L 35.421,61.647 r0 bottom value=1.00
R9 "RC0603FR-0751KL" 0603L 35.421,64.009 r0 bottom value=51.0k
R10 "RC1206FR-07205RL" 1206 15.646,53.045 r270 bottom value=205
R11 "CRCW08050000Z0EAHP" 0805_HV 32.766,40.357 r270 top value=0
R12 "CRCW060310K0FKEA" 0603 38.989,45.818 r180 top value=10.0k
R13 "ERJ-3RQF2R2V" 0603L 25.886,57.752 r90 bottom value=2.20
R14 "CRCW1206324KFKEA" 1206 11.176,65.628 r90 top value=324k
R15 "CRCW12061K65FKEA" 1206L 16.002,60.751 r270 top value=1.65k
R16 "CRCW12061K65FKEA" 1206L 16.002,55.758 r270 top value=1.65k
R17 "CRCW12061K65FKEA" 1206L 20.805,54.408 r0 top value=1.65k
R18 "CRCW1206324KFKEA" 1206 11.176,60.368 r90 top value=324k
R19 "RC0603FR-071K21L" 0603L 100.572,25.991 r90 bottom value=1.21k
R20 "CRCW1206324KFKEA" 1206 11.176,54.958 r90 top value=324k
R21 "CRCW0603100KFKEA" 0603 16.347,44.703 r90 bottom value=100k
R22 "CRCW0603649KFKEA" 0603 20.396,45.008 r180 top value=649k
R23 "CRCW060349R9FKEA" 0603 114.319,29.749 r0 bottom value=49.9
R24 "CRCW06034K99FKEA" 0603 92.202,24.789 r90 bottom value=4.99k
R25 "CRCW060320K0FKEA" 0603 102.464,25.893 r90 bottom value=20.0k
R26 "CRCW060316K5FKEA" 0603 107.5,29.74 r0 bottom value=16.5k
R27 "CRCW04020000Z0ED" 0402 24.768,35.588 r270 top value=0
R28 "CRCW06034K75FKEA" 0603 28.245,42.708 r90 bottom value=4.75k
R29 "CRCW060311K0FKEA" 0603 17.403,41.153 r90 bottom value=11.0k
R30 "CRCW0603162KFKEA" 0603 20.396,41.153 r90 bottom value=162k
R31 "RC0603FR-072K05L" 0603L 102.464,22.651 r90 bottom value=2.05k
R32 "CRCW06034K99FKEA" 0603 23.938,40.11 r0 bottom value=4.99k
R33 "RG1608P-153-B-T5" 0603 32.811,35.295 r0 bottom value=15.0k
R34 "CRCW060375K0FKEA" 0603 109.529,24.085 r90 bottom value=75.0k
R35 "CRCW06030000Z0EA" 0603 92.964,19.028 r0 top value=0
R36 "CRCW06030000Z0EA" 0603 22.951,35.388 r270 top value=0
R37 "CRCW06038K06FKEA" 0603 106.55,25.893 r270 bottom value=8.06k
R38 "B57371V2474J060" FP-B57371V2474J060_0603-MFG 27.59,37.362 r180 bottom value=470k
R39 "RG1608P-153-B-T5" 0603 27.445,38.962 r180 bottom value=15.0k
R40 "CRCW06032K00FKEA" 0603 109.529,20.571 r90 bottom value=2.00k
R41 "CRCW06030000Z0EA" 0603 22.423,40.801 r0 top value=0
R42 "CRCW06030000Z0EA" 0603 20.816,38.366 r270 top value=0
SGND "5011" Keystone5011 165.989,57.347 r0 top
SW "5012" Keystone5012 68.58,91.44 r0 top
T2 "CXS70-14-C" Panduit_CXS70-14-C 156.737,24.691 r180 top
T3 "CXS70-14-C" Panduit_CXS70-14-C 157.306,67.599 r180 top
TP1 "5125" Keystone5125 110.899,55.616 r0 top
TP2 "5125" Keystone5125 110.899,48.216 r0 top
TP3 "5125" Keystone5125 80.899,55.616 r0 top
TP4 "5003" Keystone5003 56.391,65.616 r90 top
TP5 "5003" Keystone5003 71.631,65.616 r90 top
TP6 "5125" Keystone5125 80.899,65.616 r0 top
TP7 "5125" Keystone5125 110.899,43.207 r0 top
TP8 "5125" Keystone5125 110.899,38.216 r0 top
TP9 "5125" Keystone5125 80.899,38.216 r0 top
TP10 "5125" Keystone5125 110.899,65.616 r90 top
TP11 "5125" Keystone5125 110.899,60.616 r90 top
TP12 "5125" Keystone5125 80.899,43.216 r0 top
TP13 "5125" Keystone5125 80.899,48.216 r0 top
TP14 "5125" Keystone5125 80.899,60.616 r0 top
TP15 "5003" Keystone5003 56.391,69.426 r90 top
TP16 "5003" Keystone5003 56.391,73.236 r90 top
TP17 "5003" Keystone5003 56.391,77.046 r90 top
TP18 "5003" Keystone5003 71.631,69.426 r90 top
TP19 "5003" Keystone5003 71.631,73.236 r90 top
TP20 "5003" Keystone5003 71.631,77.046 r90 top
TSET "5012" Keystone5012 4.369,40.311 r270 top
U1 "UCC256602DDBR" DDB0014A-MFG 24.433,49.016 r90 bottom
U2 "ISOM8110DFG" DFG0004A-MFG 97.282,22.689 r180 bottom value=80V
U3 "TLVH431AQDBVRQ1" DBV0005A_N 106.151,20.469 r0 bottom
VAUX "5010" Keystone5010 44.043,41.266 r0 top
Vin "5010" Keystone5010 4.496,88.208 r0 top (schematic designator VIN)
Vout "5010" Keystone5010 159.994,14.139 r0 top (schematic designator VOUT)

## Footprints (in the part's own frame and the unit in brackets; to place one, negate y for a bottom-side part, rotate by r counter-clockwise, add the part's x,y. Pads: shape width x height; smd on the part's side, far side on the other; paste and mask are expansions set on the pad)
0402 [mm] "0402 from SM-752 data"
  rect 0.8x0.6 smd: 1(-0.6,0) 2(0.6,0)
  silkscreen extent -1.22,-0.52 1.22,0.52, body extent -0.55,-0.3 0.55,0.3, height 0.6
0603 [mm] "0603 from SM-752 data"
  rect 1x0.95 smd: 1(-0.8,0) 2(0.8,0)
  silkscreen extent -1.52,-0.69 1.52,0.69, body extent -0.87,-0.47 0.87,0.47, height 1
0603L [mm] "0603 from SM-752 data"
  rect 0.8x0.85 smd: 1(-0.7,0) 2(0.7,0)
  silkscreen extent -0.07,-0.33 0.07,0.33, body extent -0.87,-0.47 0.87,0.47, height 1
0805_HV [mil] "0805 with 30mil clearance between pads"
  rect 50x63 smd: 1(-40,0) 2(40,0)
  silkscreen extent -74,-40 74,40, body extent -43,-29 43,29, height 57
0805L [mm] "0805 from SM-752 data"
  rect 1.1x1.4 smd: 1(-0.75,0) 2(0.75,0)
  body extent -1.1,-0.72 1.1,0.72, height 1.45
1206 [mm] "1206 from SM-752 data"
  rect 1.3x1.85 smd: 1(-1.45,0) 2(1.45,0)
  silkscreen extent -2.4,-1.21 2.4,1.21, body extent -1.7,-0.9 1.7,0.9, height 1.35
1206_180 [mm] "1206_180"
  rect 1.1x1.6 smd: 1(-1.7,0) 2(1.7,0)
  silkscreen extent -0.9,-1 0.9,1, body extent -1.75,-0.95 1.75,0.95, height 1.8
1206_180L [mm] "1206_180"
  rect 1.1x1.75 smd: 1(-1.35,0) 2(1.35,0)
  silkscreen extent -0.4,-0.77 0.4,0.77, body extent -1.75,-0.95 1.75,0.95, height 1.8
1206L [mm] "1206 from SM-752 data"
  rect 1.1x1.75 smd: 1(-1.35,0) 2(1.35,0)
  silkscreen extent -0.4,-0.77 0.4,0.77, body extent -1.7,-0.9 1.7,0.9, height 1.35
CAPRR1500W80L1800T500H1050 [mm] "EPCOS"
  round 1.55 hole 1.05: 1(-7.5,0) 2(7.5,0)
  silkscreen extent -9.1,-2.6 9.1,2.6, body extent -9,-2.5 9,2.5, height 10.5
DBV0005A_N [mm] "SOT23, 5-Leads, Body 2.9x1.6mm, Pitch 0.95mm, Lead Span 2.8mm, IPC Medium Density"
  rrect17% 1x0.6 smd: 1(-1.375,0.95) 2(-1.375,0) 3(-1.375,-0.95) 4(1.375,-0.95) 5(1.375,0.95)
  silkscreen extent -0.25,-1.55 0.25,1.55, body extent -1.42,-1.46 1.42,1.46, height 1.09
DDB0014A-MFG [mm]
  rrect17% 1.55x0.6 smd paste+0 mask+0: 1(-2.7,4.445) 3(-2.7,1.905) 4(-2.7,0.635) 5(-2.7,-0.635) 6(-2.7,-1.905) 7(-2.7,-3.175) 8(-2.7,-4.445) 9(2.7,-4.445) 10(2.7,-3.175) 11(2.7,-1.905) 12(2.7,-0.635) 14(2.7,1.905) 15(2.7,3.175) 16(2.7,4.445)
  silkscreen extent -4.12,-5 2,5, body extent -3.01,-4.95 3.01,4.95, height 1.75
DFG0004A-MFG [mm]
  rrect17% 1.5x0.6 smd paste+0 mask+0: 1(-3,1.27) 2(-3,-1.27) 3(3,-1.27) 4(3,1.27)
  silkscreen extent -4.43,-1.81 1.85,1.81, body extent -3.51,-1.76 3.51,1.76, height 2.65
FP-ALA8AD121BC500_RADIAL-MFG [mm]
  rrect3% 3.05x3.05 hole 2 paste-2539.97 mask+0: 1(-5,0)
  round 3.05 hole 2 paste-2539.97 mask+0: 2(5,0)
  silkscreen extent -13,-13 13,13, body extent -13.1,-13.1 13.1,13.1, height 0.25
FP-B32641B1682J000_RADIAL-MFG [mm] "Recommended Land Pattern"
  rrect8% 1.3x1.3 hole 0.8 paste-2539.97 mask+0: 1(-5,0)
  round 1.3 hole 0.8 paste-2539.97 mask+0: 2(5,0)
  body extent -6.6,-3.1 6.6,3.1, height 0.25
FP-B57371V2474J060_0603-MFG [mm]
  rrect10% 1x1 smd paste+0 mask+0: 1(-1,0) 2(1,0)
  silkscreen extent -0.13,-0.48 0.13,0.48, body extent -0.8,-0.4 0.8,0.4, height 0.9
FP-C1206C302J5GACTU_1206-MFG [mm]
  rrect11% 0.95x1.7 smd paste+0 mask+0: 1(-1.4,0) 2(1.4,0)
  silkscreen extent -0.55,-0.9 0.55,0.9, body extent -1.6,-0.8 1.6,0.8, height 0.88
FP-CGA3E2X7R1H103K080AA_0603-MFG [mm]
  rrect14% 0.7x0.7 smd paste+0 mask+0: 1(-0.7,0) 2(0.7,0)
  silkscreen extent -0.95,-0.72 0.95,0.72, body extent -0.8,-0.4 0.8,0.4, height 1.1
FP-CNA6P1X7R2A475K250AE_1210-MFG [mm]
  rrect9% 1.1x2.2 smd paste+0 mask+0: 1(-1.65,0) 2(1.65,0)
  body extent -2.3,-1.5 2.3,1.5, height 0.25
FP-CS95ZU2GA332MANKA_RADIAL-MFG [mm]
  rrect8% 1.3x1.3 hole 0.8 paste-2539.97 mask+0: 1(-3.75,0)
  round 1.3 hole 0.8 paste-2539.97 mask+0: 2(3.75,0)
  silkscreen extent -6,-3.5 6,3.5, body extent -6.1,-3.6 6.1,3.6, height 0.25
FP-FDD86252_D2PAK-MFG [mm]
  rrect8% 1.25x2.85 smd paste+0 mask+0: 1(-2.28,-4.112) 3(2.28,-4.112)
  rrect2% 5.55x6.5 smd paste+0 mask+0: 4(0,2.288)
  silkscreen extent -3.36,-2.28 3.36,3.94, body extent -3.27,-4.98 3.27,4.98, height 2.52
FP-HHXF630ARA820MJA0G_RADIAL-MFG [mm]
  rrect5% 4.4x2.2 smd paste+0 mask+0: 1(-4.45,0) 2(4.45,0)
  silkscreen extent -7.32,-5.25 5.25,5.25, body extent -6.9,-5.5 6.9,5.5, height 0.25
FP-V35PWM153-M3_I_TO-252AE-MFG [mm]
  rrect7% 1.4x1.9 smd paste+0 mask+0: 1(-2.29,-3.95) 2(2.29,-3.95)
  rrect2% 6.1x5.97 smd paste+0 mask+0: 3(0,1.915)
  silkscreen extent -3.16,-2.66 3.16,-1.45, body extent -3.1,-4.53 3.1,4.52, height 1.6
IEC_HighVoltage_Small [mm]
  silkscreen extent -2.72,-2.24 2.72,2.47
IEC_HotSurface_Small [mm]
  silkscreen extent -2.72,-2.36 2.72,2.35
Keystone5003 [mil] "For Keystone 500x miniature loop terminals"
  round 80 hole 40: 1(0,0)
  silkscreen extent -52,-52 52,52, body extent -49,-49 49,49, height 182
Keystone5010 [mil] "Keystone Multipurpose loops"
  round 87 hole 63: 1(0,0)
  silkscreen extent -70,-70 70,70, body extent -63,-63 63,62, height 319
Keystone5011 [mil] "Keystone Multipurpose loops"
  round 87 hole 63: 1(0,0)
  silkscreen extent -70,-70 70,70, body extent -63,-63 63,62, height 319
Keystone5012 [mil] "Keystone Multipurpose loops"
  round 87 hole 63: 1(0,0)
  silkscreen extent -70,-70 70,70, body extent -63,-63 63,62, height 319
Keystone5013 [mil] "Keystone Multipurpose loops"
  round 87 hole 63: 1(0,0)
  silkscreen extent -70,-70 70,70, body extent -63,-63 63,62, height 319
Keystone5125 [mil] "Keystone Multipurpose loops"
  round 87 hole 63: 1(0,0)
  silkscreen extent -70,-70 70,70, body extent -63,-63 63,62, height 319
On-Shore_ED120_2DS [mm] "ONSHORE"
  rrect5% 2x2 hole 1.25: 1(-2.54,0)
  round 2 hole 1.25: 2(2.54,0)
  silkscreen extent -5.6,-4 5.12,5, body extent -5.78,-4 5.08,5, height 13
Panduit_CXS70-14-C [mil] "Panduit"
  rect 770x500 hole 270 copper offset -74.8,0 paste-99999: 1(0,0)
  body extent -960,-250 310,250, height 684
SM_RADIAL_F [mm] "8 x 10.2mm:  Panasonic F"
  rect 4x2 smd: 1(-3.55,0) 2(3.55,0)
  silkscreen extent -4.25,-4.25 4.25,4.25, body extent -4.25,-4.25 4.25,4.25, height 10.5
SMA [mm] "Molded Diode, 2-Leads, Body 4.3x2.6mm, IPC Medium Density, based on OnSemi component dimensions and land pattern"
  rect 2x2 smd: 1(-2,0) 2(2,0)
  silkscreen extent -3.66,-1.57 2.79,1.57, body extent -2.6,-1.3 2.6,1.3, height 2.42
SMAF [mm] "SMD, 2-Leads, Body 3.8x2.5mm"
  rect 1.24x1.89 smd: 1(-2.04,0) 2(2.04,0)
  silkscreen extent -3.4,-1.3 2.8,1.3, body extent -2.35,-1.25 2.35,1.25, height 1
SOD-123 [mm] "On Semi recommended land pattern"
  rect 0.915x1.22 smd: 1(-1.637,0) 2(1.637,0)
  silkscreen extent -2.74,-1.17 2.03,1.17, body extent -1.93,-0.9 1.93,0.9, height 1.35
SOD-123W [mm] "NXP recommended land pattern"
  rect 1.2x1.2 smd paste-0.05: 1(-1.4,0) 2(1.4,0)
  silkscreen extent -2.64,-1.14 1.68,1.14, body extent -1.85,-0.95 1.85,0.95, height 1.1
SOT-223 [mm] "SOT223/SC73, 4-Leads, Body 6.5x3.5mm, Pitch 2.3mm, Lead Span 7mm, IPC Medium Density"
  rrect10% 2.4x1 smd: 1(-2.9,2.3) 2(-2.9,0) 3(-2.9,-2.3)
  rrect4% 2.4x3.3 smd: 4(2.9,0)
  silkscreen extent -3.33,-3.35 1.4,3.35, body extent -3.5,-3.25 3.5,3.25, height 1.62
SOT-363 [mm]
  rect 0.6x0.42 smd mask+0.051: 1(-0.95,0.65) 2(-0.95,0) 3(-0.95,-0.65) 4(0.95,-0.65) 5(0.95,0) 6(0.95,0.65)
  silkscreen extent -0.38,-1.02 0.38,1.02, body extent -1.1,-1.1 1.1,1.1, height 1.12
WEEE_Minimum [mm] "WEEElie bin"
  silkscreen extent -2.42,-4.38 2.52,2.65

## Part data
5V VAUX Vin Vout: library part CMP-0055147-2, "Test Point, Multipurpose, Red, TH", Color=Red, Manufacturer="Keystone Electronics", Supplier Part Number 1=36-5010-ND
BLK HG HV I_opt ISNS LG LL OVP_OTP SW TSET: library part CMP-0055149-2, "Test Point, Multipurpose, White, TH", Color=White, Manufacturer="Keystone Electronics", Supplier Part Number 1=36-5012-ND
C1 C12: library part CMP-0124191-1, "Metallized Polypropylene Capacitors (MKP/MFP), 0.0068uF, 1600V DC, 6mm(W) x 12mm(H) x 13mm(L)"
C1 C12: library part CMP-0012454-3, "CAP, Film, 0.033 uF, 630 V, +/- 10%, TH", Cap_Case=CAP_14x13.0x6mm, Manufacturer=TDK, Tolerance_%=10%, Value1=Unknown, Value2=630V, ValueDisplayed=0.033uF
C2 C16: library part CMP-0008098-2, "CAP, CERM, 1200 pF, 100 V, +/- 5%, C0G/NP0, 0805", Cap_Case=0805, Manufacturer=MuRata, Supplier Part Number 1=GRM2165C2A122JA01D-ND, TempCo=C0G/NP0, Tolerance_%=5%, Value1=Unknown, Value2=100V, ValueDisplayed=DNP
C3: library part CMP-0122768-1, "120 µF 500 V Aluminum Electrolytic Capacitors Radial, Can - Snap-In 1.73Ohm @ 100Hz 5000 Hrs @ 105°C", Digikey Part Number=399-ALA8AD121BC500-ND, Leakage Current=180uA, Manufacturer=KEMET, Mouser Part Number=80-ALA8AD121BC500, Operating Temperature Range="-40°C to +105°C", Tolerance_%=20%, ValueDisplayed=120uF
C4: library part CMP-0087262-1, "CAP CER 4.7UF 100V X7R 1210", Manufacturer=TDK, TempCo=15%, Tolerance_%=10%
C5 C6: library part CMP-0122751-1, "82 µF 63 V Aluminum - Polymer Capacitors Radial, Can - SMD 22mOhm 3000 Hrs @ 135°C", Digikey Part Number=565-HHXF630ARA820MJA0GCT-ND, Leakage Current=51.6uA, Manufacturer="United Chemi-Con", Mouser Part Number=661-HHXF630ARA820MJA, Operating Temperature Range="-55°C to +135°C", Tolerance_%=20%, ValueDisplayed=DNP
C7: library part CMP-0008885-2, "CAP, CERM, 150 pF, 630 V, +/- 5%, C0G/NP0, 1206", Cap_Case=1206, Manufacturer=MuRata, Supplier Part Number 1=490-5274-1-ND, TempCo=C0G/NP0, Tolerance_%=5%, Value1=Unknown, Value2=630V, ValueDisplayed=150pF
C8 C9: library part CMP-0122751-1, "82 µF 63 V Aluminum - Polymer Capacitors Radial, Can - SMD 22mOhm 3000 Hrs @ 135°C", Digikey Part Number=565-HHXF630ARA820MJA0GCT-ND, Leakage Current=51.6uA, Manufacturer="United Chemi-Con", Mouser Part Number=661-HHXF630ARA820MJA, Operating Temperature Range="-55°C to +135°C", Tolerance_%=20%, ValueDisplayed=82uF
C10: library part CMP-0860440-1, "CAP, CERM, 0.1 µF, 100 V,+/- 10%, X7R, AEC-Q200 Grade 1, 0805", Cap_Case=0805, Manufacturer=MuRata, TempCo=X7R, Tolerance_%=10%, Value2=100V, ValueDisplayed=0.1µF
C11: library part CMP-0008009-2, "CAP, CERM, 100 pF, 100 V, +/- 5%, C0G/NP0, AEC-Q200 Grade 1, 0805", Cap_Case=0805, Manufacturer=MuRata, Supplier Part Number 1=490-8035-1-ND, TempCo=C0G/NP0, Tolerance_%=5%, Value1=Unknown, Value2=100V, ValueDisplayed=100pF
C13: library part CMP-0010717-1, "CAP, AL, 330 uF, 25 V, +/- 20%, 0.16 ohm, AEC-Q200 Grade 2, SMD", Cap_Case=F, Manufacturer=Panasonic, Supplier Part Number 1=PCE3803CT-ND, Tolerance_%=20%, Value1="0.16 ohm", Value2=25V, ValueDisplayed=330uF
C14: library part CMP-0008462-2, "CAP, CERM, 100 pF, 100 V, +/- 5%, C0G/NP0, 1206", Cap_Case=1206, Manufacturer=AVX, Supplier Part Number 1=478-1444-1-ND, TempCo=C0G/NP0, Tolerance_%=5%, Value1="0.701 ohm", Value2=100V, ValueDisplayed=100pF
C15: library part CMP-0081062-1, "CAP, CERM, 10 µF, 25 V,+/- 5%, X7R, AEC-Q200 Grade 1, 1206", Cap_Case=1206_180, Manufacturer=Kemet, Supplier Part Number 1=399-15734-1-ND, TempCo=X7R, Tolerance_%=5%, Value2=25V, ValueDisplayed=10µF
C17: library part CMP-0097517-1, "Capacitor Ceramic 0.0033uF 440V/300V 20% 7.5mm Radial Bulk", Digikey Part Number=445-15878-ND, Manufacturer=TDK, Mouser Part Number=810-CS95ZU2GA332MANA, Operating Temperature Range="-55°C to +125°C", TempCo=+22/-56%, Temperature Characteristic=Z5U, Tolerance_%=20%, ValueDisplayed=DNP, Voltage Ac Rating X=440V, Voltage Ac Rating Y=300V
C18: library part CMP-0007883-2, "CAP, CERM, 2.2 uF, 35 V, +/- 10%, X7R, 0805", Cap_Case=0805, Manufacturer=TDK, Supplier Part Number 1=445-14547-1-ND, TempCo=X7R, Tolerance_%=10%, Value1=Unknown, Value2=35V, ValueDisplayed=DNP
C19: library part CMP-0007883-2, "CAP, CERM, 2.2 uF, 35 V, +/- 10%, X7R, 0805", Cap_Case=0805, Manufacturer=TDK, Supplier Part Number 1=445-14547-1-ND, TempCo=X7R, Tolerance_%=10%, Value1=Unknown, Value2=35V, ValueDisplayed=2.2uF
C20: library part CMP-0008693-2, "CAP, CERM, 4.7 uF, 25 V, +/- 10%, X7R, 1206", Cap_Case=1206, Manufacturer=TDK, Supplier Part Number 1=445-14797-1-ND, TempCo=X7R, Tolerance_%=10%, Value1=Unknown, Value2=25V, ValueDisplayed=4.7uF
C21: library part CMP-0064950-2, "CAP, CERM, 0.1 uF, 25 V,+/- 5%, C0G/NP0, 1206", Cap_Case=1206, Manufacturer=MuRata, Supplier Part Number 1=490-1767-1-ND, TempCo=C0G/NP0, Tolerance_%=5%, Value1=Unknown, Value2=25V, ValueDisplayed=0.1uF
C22: library part CMP-0006941-4, "CAP, CERM, 4700 pF, 100 V, +/- 5%, C0G/NP0, 0603", Cap_Case=0603, Manufacturer=Kemet, Supplier Part Number 1=399-9974-1-ND, TempCo=C0G/NP0, Tolerance_%=5%, Value1=Unknown, Value2=100V, ValueDisplayed=DNP
C23: library part CMP-0097473-1, "Cap Ceramic 10nF 50V X7R 10% Pad SMD 0603 +125°C Automotive T/R", Manufacturer=TDK, Operating Temperature Range="-55°C to +125°C", TempCo=0.15, Temperature Characteristic=X7R, Tolerance_%=0.1%, ValueDisplayed=10nF
C24 C29: library part CMP-0006976-5, "CAP, CERM, 1000 pF, 50 V, +/- 10%, X7R, 0603", Cap_Case=0603, Manufacturer=Kemet, Supplier Part Number 1=399-5348-1-ND, TempCo=X7R, Tolerance_%=10%, Value1=Unknown, Value2=50V, ValueDisplayed=1000pF
C25: library part CMP-0006982-4, "CAP, CERM, 220 pF, 50 V, +/- 10%, X7R, 0603", Cap_Case=0603, Manufacturer=Kemet, Supplier Part Number 1=399-5342-1-ND, TempCo=X7R, Tolerance_%=10%, Value1=Unknown, Value2=50V, ValueDisplayed=220pF
C26: library part CMP-0006983-4, "CAP, CERM, 2200 pF, 50 V, +/- 10%, X7R, 0603", Cap_Case=0603, Manufacturer=Kemet, Supplier Part Number 1=399-5341-1-ND, TempCo=X7R, Tolerance_%=10%, Value1=Unknown, Value2=50V, ValueDisplayed=2200pF
C27: library part CMP-0120451-1, "C1206 3,000 pF C0G 5.00% 50 V", Digikey Part Number=C1206C302J5GACTU-ND, Manufacturer=KEMET, Mouser Part Number=80-C1206C302J5G, Operating Temperature Range="-55°C to +150°C", TempCo=15%, Temperature Characteristic=C0G, Tolerance_%=0.05%, ValueDisplayed=3nF
C28: library part CMP-0007486-5, "CAP, CERM, 680 pF, 100 V, +/- 10%, X7R, 0603", Cap_Case=0603, Manufacturer=MuRata, Supplier Part Number 1=490-1469-1-ND, TempCo=X7R, Tolerance_%=10%, Value1=Unknown, Value2=100V, ValueDisplayed=680pF
C30: library part CMP-0007141-5, "CAP, CERM, 0.047 uF, 25 V, +/- 10%, X7R, AEC-Q200 Grade 1, 0603", Cap_Case=0603, Manufacturer=MuRata, Supplier Part Number 1=490-8018-1-ND, TempCo=X7R, Tolerance_%=10%, Value1=Unknown, Value2=25V, ValueDisplayed=0.047uF
D1 D4: library part CMP-0029001-2, "Diode, Ultrafast, 100 V, 0.15 A, SOD-123", Manufacturer="Diodes Inc.", Value1=0.15A, Value2=1.25V
D2 D5: library part CMP-0049616-2, "Diode 150 V 35A Surface Mount SlimDPAK", Digikey Part Number=112-V35PWM153-M3/ICT-ND, Forward Current=35A, Manufacturer=Vishay, Max Surge Forward Current=260A, Mouser Part Number=78-V35PWM153-M3/I, Operating Temperature Range="-40°C to +175°C", Part Number=V35PWM153-M3/I, Peak Reverse Current=0.2mA, ValueDisplayed=1420pF
D3: library part CMP-0028977-2, "Diode, Schottky, 100 V, 2 A, AEC-Q101, SOD-123W", Manufacturer=Nexperia, Value1=2A, Value2=0.83V
D6: library part CMP-0005756-4, "Diode, Zener, 20 V, 500 mW, SOD-123", Manufacturer="Diodes Inc.", Power_W=500mW, Value1=0.5W
D7: library part CMP-0029162-2, "Diode, Ultrafast, 600 V, 1 A, AEC-Q101, SMAF", Manufacturer="Fairchild Semiconductor", Value1=1A, Value2=1.7V
D8: library part CMP-0005526-4, "Diode, Zener, 18 V, 1 W, AEC-Q101, SMA", Manufacturer="Diodes Inc.", Power_W=1W
D9: library part CMP-0077577-3, "Diode, Zener, 17 V, 500 mW, AEC-Q101, SOD-123", Manufacturer=Vishay-Semiconductor, Power_W=500mW, Value1=0.5W
Inj: library part CMP-0055150-2, "Test Point, Multipurpose, Orange, TH", Color=Orange, Manufacturer="Keystone Electronics", Supplier Part Number 1=36-5013-ND
J1 J2: library part CMP-0074910-1, "Terminal Block, 5.08 mm, 2x1, Brass, TH", Color=Blue, Current_A=15A, Manufacturer="On-Shore Technology", Supplier Part Number 1=ED1609-ND, Voltage_V=300V
LOGO1: library part CMP-0074835-1, "IEC 61010-1 High Voltage Warning"
Logo2: library part CMP-0074837-2, "IEC 61010-1 Hot Surface Warning", Manufacturer="Texas Instruments"
Logo3: library part CMP-0074769-1
PGND SGND: library part CMP-0055148-2, "Test Point, Multipurpose, Black, TH", Color=Black, Manufacturer="Keystone Electronics", Supplier Part Number 1=36-5011-ND
Q1 Q2: library part CMP-0122070-1, "N-Channel 650 V, 20A (Tc), 162W (Tc) Surface Mount TO−263", Drain To Source Breakdown Voltage=650V, Input Capacitace At Vds="1605pF @ 400V", Manufacturer="On Semi", Operating Temperature Range="-55°C to +150°C", Power_W=162W, Pulse Drain Current=50A, Typ Forward Diode Voltage=1.0V
Q3: library part CMP-0000393-2, "Transistor, NPN, 60 V, 3 A, SOT-223", Manufacturer=Zetex, Supplier Part Number 1=FZT651CT-ND, Value1="3 A", Value2=300
Q4: library part CMP-0000396-2, "Transistor, Dual NPN, 40 V, 0.2 A, SOT-363", Manufacturer="Diodes Inc.", Supplier Part Number 1=MMDT3904-FDICT-ND, Value1="0.2 A", Value2=300
R1 R6: library part CMP-0025821-4, "RES, 4.7, 5%, 0.1 W, AEC-Q200 Grade 0, 0603", Manufacturer=Vishay-Dale, Power_W=100mW, Supplier Part Number 1=541-4.7GCT-ND, TempCo="200 ppm/C", Tolerance_%=5%, Value2=0.1W, Value_Code=4R70, ValueDisplayed=4.7
R2 R7: library part CMP-0017851-2, "RES, 10.0, 1%, 0.25 W, 1206", Manufacturer="Yageo America", Power_W=250mW, Supplier Part Number 1=311-10.0FRCT-ND, TempCo="200 ppm/C", Tolerance_%=1%, Value2=0.25W, Value_Code=10R0, ValueDisplayed=DNP
R3 R8: library part CMP-0022900-4, "RES, 1.00, 1%, 0.1 W, 0603", Manufacturer=Yageo, Power_W=100mW, Supplier Part Number 1=311-1.00HRCT-ND, TempCo="200 ppm/C", Tolerance_%=1%, Value2=0.1W, Value_Code=1R00, ValueDisplayed=1.00
R4 R9: library part CMP-0023167-5, "RES, 51.0 k, 1%, 0.1 W, 0603", Manufacturer=Yageo, Power_W=100mW, Supplier Part Number 1=311-51.0KHRCT-ND, TempCo="100 ppm/C", Tolerance_%=1%, Value2=0.1W, Value_Code=51k0, ValueDisplayed=51.0k
R5: library part CMP-0018748-3, "RES, 0, 5%, 0.25 W, AEC-Q200 Grade 0, 1206", Manufacturer=Panasonic, Power_W=250mW, Supplier Part Number 1=P0.0ECT-ND, TempCo="600 ppm/C", Tolerance_%=5%, Value2=0.25W, Value_Code=0000, ValueDisplayed=0
R10: library part CMP-0018063-2, "RES, 205, 1%, 0.25 W, 1206", Manufacturer="Yageo America", Power_W=250mW, Supplier Part Number 1=311-205FRCT-ND, TempCo="100 ppm/C", Tolerance_%=1%, Value2=0.25W, Value_Code=205R, ValueDisplayed=205
R11: library part CMP-0020443-3, "RES, 0, 5%, 0.333 W, AEC-Q200 Grade 0, 0805", Manufacturer=Vishay-Dale, Power_W=333mW, Supplier Part Number 1=541-0.0TBCT-ND, TempCo="200 ppm/C", Tolerance_%=5%, Value2=0.333W, Value_Code=0000, ValueDisplayed=DNP
R12: library part CMP-0021998-4, "RES, 10.0 k, 1%, 0.1 W, AEC-Q200 Grade 0, 0603", Manufacturer=Vishay-Dale, Power_W=100mW, Supplier Part Number 1=541-10.0KHCT-ND, TempCo="100 ppm/C", Tolerance_%=1%, Value2=0.1W, Value_Code=10k0, ValueDisplayed=10.0k
R13: library part CMP-0022711-2, "RES, 2.20, 1%, 0.1 W, 0603", Manufacturer=Panasonic, Power_W=100mW, Supplier Part Number 1=P2.2AJCT-ND, TempCo="200 ppm/C", Tolerance_%=1%, Value2=0.1W, Value_Code=2R20, ValueDisplayed=2.20
R14 R18 R20: library part CMP-0016907-3, "RES, 324 k, 1%, 0.25 W, AEC-Q200 Grade 0, 1206", Manufacturer=Vishay-Dale, Power_W=250mW, Supplier Part Number 1=541-324KFCT-ND, TempCo="100 ppm/C", Tolerance_%=1%, Value2=0.25W, Value_Code=324k
R15 R16 R17: library part CMP-0016708-3, "RES, 1.65 k, 1%, 0.25 W, AEC-Q200 Grade 0, 1206", Manufacturer=Vishay-Dale, Power_W=250mW, Supplier Part Number 1=541-1.65KFCT-ND, TempCo="100 ppm/C", Tolerance_%=1%, Value2=0.25W, Value_Code=1k65, ValueDisplayed=1.65k
R19: library part CMP-0022871-5, "RES, 1.21 k, 1%, 0.1 W, 0603", Manufacturer=Yageo, Power_W=100mW, Supplier Part Number 1=311-1.21KHRCT-ND, TempCo="100 ppm/C", Tolerance_%=1%, Value2=0.1W, Value_Code=1k21, ValueDisplayed=DNP
R21: library part CMP-0021990-4, "RES, 100 k, 1%, 0.1 W, AEC-Q200 Grade 0, 0603", Manufacturer=Vishay-Dale, Power_W=100mW, Supplier Part Number 1=541-100KHCT-ND, TempCo="100 ppm/C", Tolerance_%=1%, Value2=0.1W, Value_Code=100k
R22: library part CMP-0022542-4, "RES, 649 k, 1%, 0.1 W, AEC-Q200 Grade 0, 0603", Manufacturer=Vishay-Dale, Power_W=100mW, Supplier Part Number 1=541-649KHCT-ND, TempCo="100 ppm/C", Tolerance_%=1%, Value2=0.1W, Value_Code=649k
R23: library part CMP-0022448-4, "RES, 49.9, 1%, 0.1 W, AEC-Q200 Grade 0, 0603", Manufacturer=Vishay-Dale, Power_W=100mW, Supplier Part Number 1=541-49.9HCT-ND, TempCo="100 ppm/C", Tolerance_%=1%, Value2=0.1W, Value_Code=49R9, ValueDisplayed=49.9
R24: library part CMP-0022458-4, "RES, 4.99 k, 1%, 0.1 W, AEC-Q200 Grade 0, 0603", Manufacturer=Vishay-Dale, Power_W=100mW, Supplier Part Number 1=541-4.99KHCT-ND, TempCo="100 ppm/C", Tolerance_%=1%, Value2=0.1W, Value_Code=4k99, ValueDisplayed=4.99k
R25: library part CMP-0022204-4, "RES, 20.0 k, 1%, 0.1 W, AEC-Q200 Grade 0, 0603", Manufacturer=Vishay-Dale, Power_W=100mW, Supplier Part Number 1=541-20.0KHCT-ND, TempCo="100 ppm/C", Tolerance_%=1%, Value2=0.1W, Value_Code=20k0, ValueDisplayed=20.0k
R26: library part CMP-0022080-4, "RES, 16.5 k, 1%, 0.1 W, AEC-Q200 Grade 0, 0603", Manufacturer=Vishay-Dale, Power_W=100mW, Supplier Part Number 1=541-16.5KHCT-ND, TempCo="100 ppm/C", Tolerance_%=1%, Value2=0.1W, Value_Code=16k5, ValueDisplayed=16.5k
R27: library part CMP-0026822-3, "RES, 0, 5%, 0.063 W, AEC-Q200 Grade 0, 0402", Manufacturer=Vishay-Dale, Power_W=63mW, Supplier Part Number 1=541-0.0JCT-ND, TempCo="200 ppm/C", Tolerance_%=5%, Value2=0.063W, Value_Code=0000, ValueDisplayed=0
R28: library part CMP-0022456-4, "RES, 4.75 k, 1%, 0.1 W, AEC-Q200 Grade 0, 0603", Manufacturer=Vishay-Dale, Power_W=100mW, Supplier Part Number 1=541-4.75KHCT-ND, TempCo="100 ppm/C", Tolerance_%=1%, Value2=0.1W, Value_Code=4k75, ValueDisplayed=4.75k
R29: library part CMP-0022016-4, "RES, 11.0 k, 1%, 0.1 W, AEC-Q200 Grade 0, 0603", Manufacturer=Vishay-Dale, Power_W=100mW, Supplier Part Number 1=541-11.0KHCT-ND, TempCo="100 ppm/C", Tolerance_%=1%, Value2=0.1W, Value_Code=11k0, ValueDisplayed=11.0k
R30: library part CMP-0022073-4, "RES, 162 k, 1%, 0.1 W, AEC-Q200 Grade 0, 0603", Manufacturer=Vishay-Dale, Power_W=100mW, Supplier Part Number 1=541-162KHCT-ND, TempCo="100 ppm/C", Tolerance_%=1%, Value2=0.1W, Value_Code=162k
